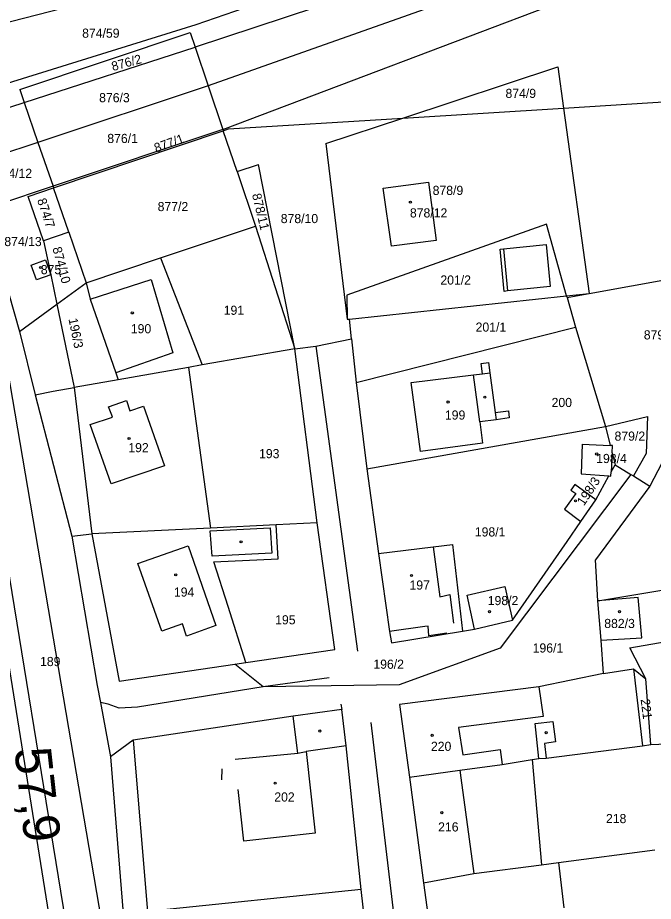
# Model space of a CAD drawing. Extents: x -563148 to -561712, y -1182311 to -1179502.
# Drawn here: x -562656.5 to -562552.1, y -1180106.8 to -1179961.9 of the extents above; entities that cross this region are included whole.
import ezdxf

# ---------------------------------------------------------------- set-up
doc = ezdxf.new("R2010")
doc.units = 0
for name, color, linetype in [('Vrstva 53', 7, 'Continuous'), ('Vrstva 55', 7, 'Continuous'), ('Vrstva 56', 7, 'Continuous'), ('Vrstva 57', 7, 'Continuous'), ('Vrstva 7', 7, 'Continuous')]:
    doc.layers.add(name, color=color, linetype=linetype)

msp = doc.modelspace()

# ---------------------------------------------------------------- linework, layer by layer
at = {"layer": 'Vrstva 53'}
msp.add_line((-562666.05, -1180017.58), (-562648.5, -1180126.87), dxfattribs=at)
at = {"layer": 'Vrstva 55'}
for p, q in [((-562622.8, -1179980.18), (-562507.68, -1179936.66)), ((-562527.07, -1179938.34), (-562625.22, -1179973.02)), ((-562574.17, -1179949.12), (-562627.35, -1179966.72)), ((-562669.72, -1179965.6), (-562631.02, -1179955.54)), ((-562619.28, -1179960.3), (-562627.21, -1179963.06)), ((-562627.21, -1179963.06), (-562666.96, -1179975.34)), ((-562656.1, -1179973.66), (-562628.17, -1179964.31)), ((-562628.17, -1179964.31), (-562627.35, -1179966.72)), ((-562655.37, -1179975.78), (-562627.35, -1179966.72)), ((-562627.35, -1179966.72), (-562625.22, -1179973.02)), ((-562593.27, -1179978.34), (-562567.82, -1179969.93)), ((-562567.82, -1179969.93), (-562566.88, -1179976.69)), ((-562656.1, -1179973.66), (-562655.37, -1179975.78)), ((-562625.22, -1179973.02), (-562653.13, -1179982.32)), ((-562625.22, -1179973.02), (-562622.8, -1179980.18)), ((-562566.88, -1179976.69), (-562518.56, -1179973.67)), ((-562665.87, -1179979.18), (-562655.37, -1179975.78)), ((-562655.37, -1179975.78), (-562653.13, -1179982.32)), ((-562593.27, -1179978.34), (-562566.88, -1179976.69)), ((-562566.88, -1179976.69), (-562562.66, -1180007.08)), ((-562621.89, -1179980.12), (-562593.27, -1179978.34)), ((-562605.88, -1179982.5), (-562593.27, -1179978.34)), ((-562622.8, -1179980.18), (-562650.66, -1179989.51)), ((-562650.58, -1179989.75), (-562622.72, -1179980.42)), ((-562622.8, -1179980.18), (-562622.72, -1179980.42)), ((-562622.72, -1179980.42), (-562621.89, -1179980.12)), ((-562620.45, -1179987.11), (-562622.72, -1179980.42)), ((-562653.13, -1179982.32), (-562663.95, -1179985.93)), ((-562653.13, -1179982.32), (-562650.66, -1179989.51)), ((-562605.88, -1179982.5), (-562602.4, -1180011.33)), ((-562620.45, -1179987.11), (-562616.94, -1179985.92)), ((-562620.45, -1179987.11), (-562617.43, -1179996.04)), ((-562611, -1180016.16), (-562616.94, -1179985.92)), ((-562650.66, -1179989.51), (-562661.87, -1179993.27)), ((-562654.74, -1179991.17), (-562650.58, -1179989.75)), ((-562650.66, -1179989.51), (-562650.58, -1179989.75)), ((-562648.08, -1179997.03), (-562650.58, -1179989.75)), ((-562652.24, -1179998.45), (-562654.74, -1179991.17)), ((-562661.8, -1179993.53), (-562656.17, -1180013.33)), ((-562569.68, -1179995.72), (-562602.43, -1180007.37)), ((-562566.38, -1180007.48), (-562569.68, -1179995.72)), ((-562648.08, -1179997.03), (-562652.24, -1179998.45)), ((-562648.08, -1179997.03), (-562645.23, -1180005.35)), ((-562633.03, -1180001.27), (-562617.43, -1179996.04)), ((-562617.43, -1179996.04), (-562611, -1180016.16)), ((-562652.24, -1179998.45), (-562651.01, -1180004.03)), ((-562654.25, -1180002.45), (-562651.87, -1180001.6)), ((-562651.87, -1180001.6), (-562651.01, -1180004.03)), ((-562645.23, -1180005.35), (-562633.03, -1180001.27)), ((-562633.03, -1180001.27), (-562626.19, -1180018.83)), ((-562562.66, -1180007.08), (-562533.63, -1180001.81)), ((-562533.63, -1180001.81), (-562552.72, -1180038.69)), ((-562653.39, -1180004.87), (-562654.25, -1180002.45)), ((-562651.01, -1180004.03), (-562653.39, -1180004.87)), ((-562651.01, -1180004.03), (-562650.05, -1180008.87)), ((-562650.05, -1180008.87), (-562645.23, -1180005.35)), ((-562645.23, -1180005.35), (-562644.57, -1180008.05)), ((-562602.43, -1180007.37), (-562602.4, -1180011.33)), ((-562602.02, -1180011.3), (-562566.38, -1180007.48)), ((-562566.38, -1180007.48), (-562562.66, -1180007.08)), ((-562566.31, -1180007.74), (-562566.38, -1180007.48)), ((-562656.17, -1180013.33), (-562650.05, -1180008.87)), ((-562650.05, -1180008.87), (-562647.18, -1180022.53)), ((-562644.57, -1180008.05), (-562640.34, -1180020.1)), ((-562566.31, -1180007.74), (-562564.94, -1180012.6)), ((-562602.4, -1180011.33), (-562602.02, -1180011.3)), ((-562601.69, -1180014.52), (-562602.02, -1180011.3)), ((-562656.17, -1180013.33), (-562653.57, -1180023.74)), ((-562600.94, -1180021.69), (-562564.94, -1180012.6)), ((-562564.94, -1180012.6), (-562560.02, -1180028.93)), ((-562607.55, -1180015.72), (-562601.69, -1180014.52)), ((-562601.69, -1180014.52), (-562600.94, -1180021.69)), ((-562611, -1180016.16), (-562626.19, -1180018.83)), ((-562611, -1180016.16), (-562607.55, -1180015.72)), ((-562607.34, -1180044.74), (-562611, -1180016.16)), ((-562628.41, -1180019.22), (-562639.97, -1180021.25)), ((-562626.19, -1180018.83), (-562628.41, -1180019.22)), ((-562628.41, -1180019.22), (-562624.81, -1180045.6)), ((-562580.4, -1180018.59), (-562579.18, -1180018.42)), ((-562580.19, -1180020.26), (-562580.4, -1180018.59)), ((-562579.18, -1180018.42), (-562578.96, -1180020.1)), ((-562640.34, -1180020.1), (-562639.97, -1180021.25)), ((-562591.91, -1180021.71), (-562581.64, -1180020.44)), ((-562581.64, -1180020.44), (-562580.19, -1180020.26)), ((-562578.96, -1180020.1), (-562578.11, -1180026.61)), ((-562639.97, -1180021.25), (-562647.18, -1180022.53)), ((-562600.94, -1180021.69), (-562599.17, -1180035.89)), ((-562590.36, -1180033.01), (-562591.91, -1180021.71)), ((-562647.18, -1180022.53), (-562644.27, -1180046.54)), ((-562653.57, -1180023.74), (-562647.59, -1180046.91)), ((-562578.11, -1180026.61), (-562575.94, -1180026.33)), ((-562575.94, -1180026.33), (-562575.79, -1180027.52)), ((-562577.96, -1180027.8), (-562580.63, -1180028.15)), ((-562575.79, -1180027.52), (-562577.96, -1180027.8)), ((-562560.02, -1180028.93), (-562553.13, -1180027.3)), ((-562553.13, -1180027.3), (-562553.3, -1180033.37)), ((-562599.17, -1180035.89), (-562560.02, -1180028.93)), ((-562580.63, -1180028.15), (-562580.18, -1180031.64)), ((-562560.02, -1180028.93), (-562559.22, -1180032.05)), ((-562580.18, -1180031.64), (-562590.36, -1180033.01)), ((-562563.8, -1180031.82), (-562563.98, -1180036.71)), ((-562563.8, -1180031.82), (-562559.22, -1180032.05)), ((-562558.86, -1180032.06), (-562559.22, -1180032.05)), ((-562558.92, -1180033.23), (-562558.86, -1180032.06)), ((-562558.92, -1180033.23), (-562558.42, -1180035.19)), ((-562553.3, -1180033.37), (-562555.42, -1180037.03)), ((-562599.17, -1180035.89), (-562597.25, -1180049.76)), ((-562559.12, -1180037.06), (-562559.08, -1180036.38)), ((-562559.08, -1180036.38), (-562558.42, -1180035.19)), ((-562558.42, -1180035.19), (-562555.82, -1180036.79)), ((-562555.82, -1180036.79), (-562577.26, -1180065.28)), ((-562563.98, -1180036.71), (-562559.44, -1180037.03)), ((-562561.61, -1180040.95), (-562559.44, -1180037.03)), ((-562559.44, -1180037.03), (-562559.12, -1180037.06)), ((-562555.82, -1180036.79), (-562555.42, -1180037.03)), ((-562555.42, -1180037.03), (-562552.72, -1180038.69)), ((-562565.04, -1180038.44), (-562565.67, -1180039.34)), ((-562565.67, -1180039.34), (-562564.86, -1180039.93)), ((-562561.61, -1180040.95), (-562565.04, -1180038.44)), ((-562552.72, -1180038.69), (-562561.64, -1180050.79)), ((-562564.86, -1180039.93), (-562566.71, -1180042.46)), ((-562564.04, -1180044.51), (-562561.61, -1180040.95)), ((-562566.71, -1180042.46), (-562564.04, -1180044.51)), ((-562614.04, -1180045.07), (-562624.81, -1180045.6)), ((-562607.34, -1180044.74), (-562614.04, -1180045.07)), ((-562613.71, -1180050.63), (-562614.04, -1180045.07)), ((-562604.43, -1180065.52), (-562607.34, -1180044.74)), ((-562566.26, -1180047.78), (-562564.04, -1180044.51)), ((-562624.81, -1180045.6), (-562644.27, -1180046.54)), ((-562644.27, -1180046.54), (-562639.82, -1180070.67)), ((-562647.59, -1180046.91), (-562643.39, -1180071.41)), ((-562575.26, -1180060.67), (-562566.26, -1180047.78)), ((-562597.25, -1180049.76), (-562588.28, -1180048.67)), ((-562588.28, -1180048.67), (-562585.1, -1180048.29)), ((-562585.1, -1180048.29), (-562583.45, -1180062.5)), ((-562624.26, -1180051.12), (-562613.71, -1180050.63)), ((-562597.25, -1180049.76), (-562595.44, -1180062.53)), ((-562561.23, -1180057.52), (-562561.64, -1180050.79)), ((-562621.92, -1180058.46), (-562624.26, -1180051.12)), ((-562582.72, -1180056.58), (-562576.54, -1180055.14)), ((-562576.54, -1180055.14), (-562575.26, -1180060.67)), ((-562561.23, -1180057.52), (-562543, -1180054.43)), ((-562581.48, -1180062.17), (-562582.72, -1180056.58)), ((-562554.62, -1180056.97), (-562561.23, -1180057.52)), ((-562560.72, -1180063.99), (-562561.23, -1180057.52)), ((-562554.06, -1180063.57), (-562554.62, -1180056.97)), ((-562619.02, -1180067.64), (-562621.92, -1180058.46)), ((-562581.48, -1180062.17), (-562575.26, -1180060.67)), ((-562595.44, -1180062.53), (-562595.11, -1180064.41)), ((-562595.11, -1180064.41), (-562583.45, -1180062.5)), ((-562583.45, -1180062.5), (-562581.48, -1180062.17)), ((-562556.02, -1180065.2), (-562534.96, -1180061.57)), ((-562560.72, -1180063.99), (-562554.06, -1180063.57)), ((-562560.35, -1180069.41), (-562560.72, -1180063.99)), ((-562619.02, -1180067.64), (-562604.43, -1180065.52)), ((-562577.26, -1180065.28), (-562593.85, -1180071.31)), ((-562553.36, -1180070.31), (-562556.02, -1180065.2)), ((-562639.82, -1180070.67), (-562620.85, -1180067.91)), ((-562620.85, -1180067.91), (-562619.02, -1180067.64)), ((-562616.19, -1180071.65), (-562620.85, -1180067.91)), ((-562560.35, -1180069.41), (-562570.95, -1180071.61)), ((-562560.35, -1180069.41), (-562555.41, -1180068.66)), ((-562555.41, -1180068.66), (-562553.92, -1180081.3)), ((-562555.41, -1180068.66), (-562553.36, -1180070.31)), ((-562593.85, -1180071.31), (-562616.19, -1180071.65)), ((-562552.56, -1180081.11), (-562553.36, -1180070.31)), ((-562643.39, -1180071.41), (-562642.88, -1180074.17)), ((-562570.95, -1180071.61), (-562593.81, -1180074.51)), ((-562642.88, -1180074.17), (-562641.2, -1180083.09)), ((-562603.24, -1180075.33), (-562611.23, -1180076.43)), ((-562602.58, -1180081.3), (-562603.24, -1180075.33)), ((-562593.81, -1180074.51), (-562592.16, -1180086.44)), ((-562611.23, -1180076.43), (-562637.52, -1180080.39)), ((-562637.52, -1180080.39), (-562635.15, -1180108.47)), ((-562600.07, -1180104.88), (-562602.58, -1180081.3)), ((-562569.76, -1180083.33), (-562553.92, -1180081.3)), ((-562553.92, -1180081.3), (-562552.56, -1180081.11)), ((-562552.56, -1180081.11), (-562549.95, -1180080.96)), ((-562641.2, -1180083.09), (-562637.95, -1180123.37)), ((-562583.89, -1180085.32), (-562576.94, -1180084.37)), ((-562576.94, -1180084.37), (-562572.02, -1180083.55)), ((-562572.02, -1180083.55), (-562570.93, -1180083.37)), ((-562572.02, -1180083.55), (-562570.5, -1180100.8)), ((-562570.93, -1180083.37), (-562569.76, -1180083.33)), ((-562592.16, -1180086.44), (-562583.89, -1180085.32)), ((-562592.16, -1180086.44), (-562589.86, -1180103.78)), ((-562567.72, -1180100.44), (-562551.91, -1180098.37)), ((-562581.62, -1180102.22), (-562570.5, -1180100.8)), ((-562570.5, -1180100.8), (-562567.72, -1180100.44)), ((-562589.86, -1180103.78), (-562581.62, -1180102.22)), ((-562589.86, -1180103.78), (-562587.64, -1180120.04)), ((-562600.07, -1180104.88), (-562635.15, -1180108.47)), ((-562598.53, -1180119.3), (-562600.07, -1180104.88))]:
    msp.add_line(p, q, dxfattribs=at)
msp.add_lwpolyline([(-562596.47, -1179989.84), (-562589.02, -1179988.86), (-562587.77, -1179998.39), (-562595.13, -1179999.36), (-562596.47, -1179989.84)], dxfattribs=at)
at = {"layer": 'Vrstva 56'}
for p, q in [((-562577.29, -1179999.83), (-562576.74, -1179999.78)), ((-562576.61, -1180006.76), (-562577.29, -1179999.83)), ((-562576.74, -1179999.78), (-562569.73, -1179999.06)), ((-562576.74, -1179999.78), (-562576.08, -1180006.69)), ((-562569.73, -1179999.06), (-562569.06, -1180005.97)), ((-562644.57, -1180008.05), (-562634.56, -1180004.82)), ((-562634.56, -1180004.82), (-562630.99, -1180016.86)), ((-562569.06, -1180005.97), (-562576.08, -1180006.69)), ((-562576.08, -1180006.69), (-562576.61, -1180006.76)), ((-562566.31, -1180007.74), (-562562.66, -1180007.08)), ((-562659.01, -1180014.55), (-562640.31, -1180124.15)), ((-562607.55, -1180015.72), (-562600.7, -1180065.75)), ((-562645.98, -1180126.03), (-562663.84, -1180016.63)), ((-562630.99, -1180016.86), (-562640.34, -1180020.1)), ((-562580.63, -1180028.15), (-562581.64, -1180020.44)), ((-562580.19, -1180020.26), (-562578.96, -1180020.1)), ((-562653.57, -1180023.74), (-562650.62, -1180023.14)), ((-562650.62, -1180023.14), (-562647.18, -1180022.53)), ((-562641.58, -1180025.67), (-562638.6, -1180024.66)), ((-562638.6, -1180024.66), (-562638.03, -1180026.37)), ((-562641.01, -1180027.08), (-562641.58, -1180025.67)), ((-562638.03, -1180026.37), (-562635.81, -1180025.58)), ((-562635.81, -1180025.58), (-562632.36, -1180035.37)), ((-562644.54, -1180028.6), (-562640.88, -1180027.37)), ((-562640.88, -1180027.37), (-562641.01, -1180027.08)), ((-562578.11, -1180026.61), (-562577.96, -1180027.8)), ((-562641.12, -1180038.32), (-562644.54, -1180028.6)), ((-562558.92, -1180033.23), (-562559.08, -1180036.38)), ((-562632.36, -1180035.37), (-562641.12, -1180038.32)), ((-562647.59, -1180046.91), (-562644.27, -1180046.54)), ((-562624.85, -1180046.01), (-562615.01, -1180045.52)), ((-562624.57, -1180050.2), (-562624.85, -1180046.01)), ((-562615.01, -1180045.52), (-562614.77, -1180049.68)), ((-562636.73, -1180051.42), (-562628.47, -1180048.51)), ((-562628.47, -1180048.51), (-562623.96, -1180061.59)), ((-562588.28, -1180048.67), (-562587.18, -1180056.88)), ((-562614.77, -1180049.68), (-562624.57, -1180050.2)), ((-562632.82, -1180062.47), (-562636.73, -1180051.42)), ((-562587.18, -1180056.88), (-562585.55, -1180056.48)), ((-562585.55, -1180056.48), (-562584.92, -1180061.2)), ((-562629.42, -1180061.27), (-562632.82, -1180062.47)), ((-562628.75, -1180063.32), (-562629.42, -1180061.27)), ((-562623.96, -1180061.59), (-562628.75, -1180063.32)), ((-562589.65, -1180061.74), (-562595.44, -1180062.53)), ((-562589.09, -1180061.66), (-562589.65, -1180061.74)), ((-562588.97, -1180063.27), (-562589.09, -1180061.66)), ((-562586.02, -1180062.82), (-562588.97, -1180063.27)), ((-562605.33, -1180070.13), (-562616.19, -1180071.65)), ((-562616.19, -1180071.65), (-562636.77, -1180074.94)), ((-562570.95, -1180071.61), (-562570.2, -1180076.48)), ((-562641.59, -1180074.48), (-562642.88, -1180074.17)), ((-562639.78, -1180075.1), (-562641.59, -1180074.48)), ((-562636.77, -1180074.94), (-562639.78, -1180075.1)), ((-562603.42, -1180074.44), (-562603.24, -1180075.33)), ((-562610.5, -1180082.53), (-562611.23, -1180076.43)), ((-562570.2, -1180076.48), (-562584.11, -1180078.31)), ((-562598.51, -1180077.5), (-562591.55, -1180135.95)), ((-562584.11, -1180078.31), (-562583.4, -1180082.79)), ((-562571.53, -1180077.63), (-562568.63, -1180077.3)), ((-562570.93, -1180083.37), (-562571.53, -1180077.63)), ((-562568.63, -1180077.3), (-562568.21, -1180080.64)), ((-562637.52, -1180080.39), (-562641.2, -1180083.09)), ((-562602.58, -1180081.3), (-562609.1, -1180082.24)), ((-562568.21, -1180080.64), (-562569.99, -1180080.93)), ((-562569.99, -1180080.93), (-562569.76, -1180083.33)), ((-562620.77, -1180083.51), (-562610.5, -1180082.53)), ((-562610.5, -1180082.53), (-562609.1, -1180082.24)), ((-562609.1, -1180082.24), (-562607.63, -1180095.61)), ((-562583.4, -1180082.79), (-562577.28, -1180081.92)), ((-562577.28, -1180081.92), (-562576.94, -1180084.37)), ((-562622.95, -1180086.9), (-562622.9, -1180085.06)), ((-562583.89, -1180085.32), (-562583.73, -1180086.53)), ((-562583.73, -1180086.53), (-562581.62, -1180102.22)), ((-562619.32, -1180096.95), (-562620.26, -1180088.48)), ((-562607.63, -1180095.61), (-562619.32, -1180096.95)), ((-562567.72, -1180100.44), (-562566.82, -1180107.87))]:
    msp.add_line(p, q, dxfattribs=at)
at = {"layer": 'Vrstva 57'}
for centre in [(-562592.01, -1179992.13), (-562652.69, -1180002.85), (-562637.65, -1180010.29), (-562585.83, -1180024.91), (-562579.79, -1180024.12), (-562638.18, -1180030.89), (-562561.44, -1180033.43), (-562564.93, -1180041.12), (-562619.8, -1180047.85), (-562630.52, -1180053.24), (-562591.83, -1180053.37), (-562579.02, -1180059.3), (-562557.69, -1180059.3), (-562606.88, -1180078.87), (-562588.45, -1180079.58), (-562569.74, -1180079.15), (-562614.21, -1180087.42), (-562586.86, -1180092.26)]:
    msp.add_circle(centre, 0.175, dxfattribs=at)

# ---------------------------------------------------------------- texts
for s, p in [('874/59', (-562645.88, -1179965.15)), ('876/3', (-562643.09, -1179975.73)), ('874/9', (-562576.41, -1179975.03)), ('876/1', (-562641.75, -1179982.42)), ('874/12', (-562660.23, -1179988.14)), ('878/9', (-562588.36, -1179990.94)), ('877/2', (-562633.49, -1179993.59)), ('878/12', (-562592.09, -1179994.63)), ('878/10', (-562613.29, -1179995.56)), ('874/13', (-562658.65, -1179999.33)), ('875', (-562652.66, -1180003.94)), ('201/2', (-562587.09, -1180005.64)), ('191', (-562622.65, -1180010.6)), ('201/1', (-562581.31, -1180013.37)), ('190', (-562637.89, -1180013.63)), ('879/1', (-562553.71, -1180014.64)), ('200', (-562568.84, -1180025.73)), ('199', (-562586.35, -1180027.79)), ('879/2', (-562558.51, -1180031.25)), ('192', (-562638.3, -1180033.14)), ('193', (-562616.85, -1180034.12)), ('198/4', (-562561.52, -1180034.92)), ('198/1', (-562581.44, -1180046.96)), ('194', (-562630.82, -1180056.83)), ('197', (-562592.16, -1180055.68)), ('198/2', (-562579.32, -1180058.22)), ('195', (-562614.21, -1180061.38)), ('882/3', (-562560.2, -1180061.98)), ('196/1', (-562571.95, -1180066)), ('189', (-562652.79, -1180068.22)), ('196/2', (-562598.09, -1180068.66)), ('220', (-562588.64, -1180082.13)), ('202', (-562614.35, -1180090.44)), ('218', (-562559.92, -1180093.98)), ('216', (-562587.46, -1180095.35))]:
    msp.add_text(s, height=1.5, dxfattribs=at).set_placement(p)
for s, rotation, p in [('876/2', 15.4146, (-562640.83, -1179970.62)), ('877/1', 19.9831, (-562633.74, -1179984.01)), ('874/7', 288.1967, (-562653.28, -1179991.75)), ('878/11', 283.548, (-562618.02, -1179990.87)), ('874/10', 284.9768, (-562650.77, -1179999.67)), ('196/3', 281.465, (-562648.13, -1180011.29)), ('198/3', 56.9264, (-562563.53, -1180042.03)), ('221', 277.3012, (-562554.24, -1180073.69))]:
    msp.add_text(s, height=1.5, rotation=rotation, dxfattribs=at).set_placement(p)
at = {"layer": 'Vrstva 7'}
msp.add_text('57,9', height=6, rotation=276.2871, dxfattribs=at).set_placement((-562657.01, -1180081.83))

doc.saveas('drawing.dxf')
